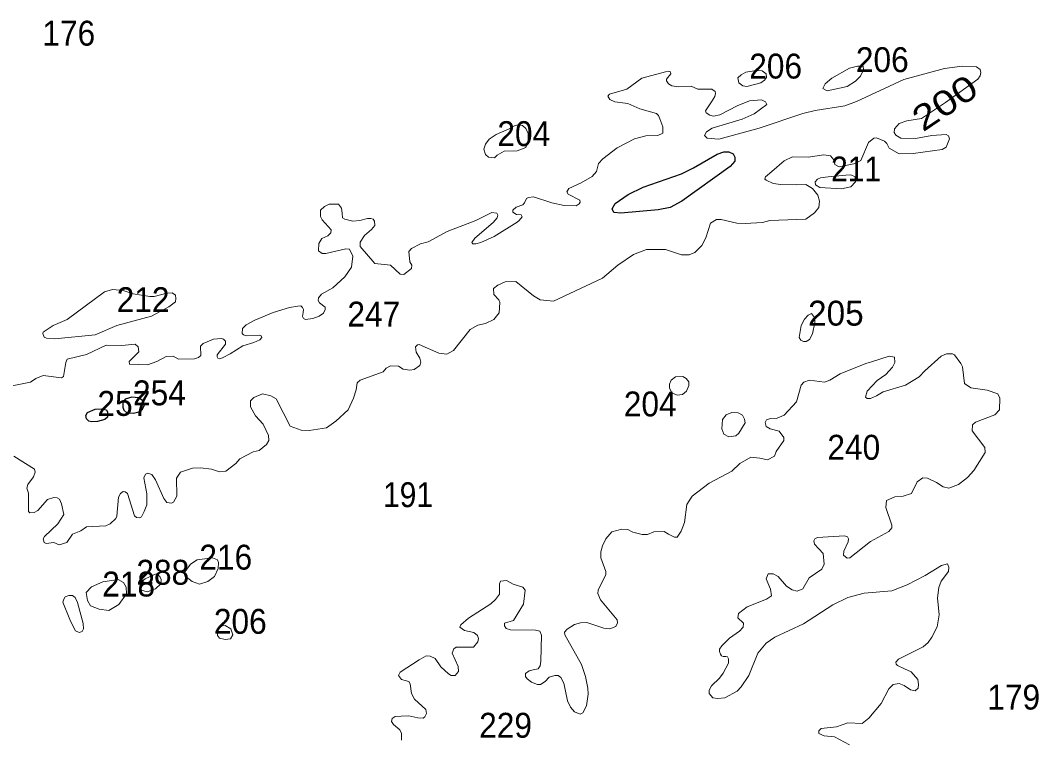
# Model space of a CAD drawing. Extents: x 499.9 to 555.3, y 9281.5 to 9336.8.
# Drawn here: x 505.67 to 512.21, y 9283.84 to 9288.46 of the extents above; entities that cross this region are included whole.
import ezdxf
from ezdxf.enums import TextEntityAlignment as Align

# ---------------------------------------------------------------- set-up
doc = ezdxf.new("R2010")
doc.units = 0
doc.header["$LTSCALE"] = 0.064
doc.layers.add('1', color=7, linetype='Continuous', lineweight=25)
doc.layers.add('2', color=7, linetype='Continuous', lineweight=13)
doc.layers.add('21', color=7, linetype='Continuous')
doc.layers.add('61', color=7, linetype='Continuous')

msp = doc.modelspace()

# ---------------------------------------------------------------- linework, layer by layer
at = {"layer": '1'}
for points in [[(509.5307, 9287.2221), (509.4853, 9287.2275), (509.4736, 9287.251), (509.4939, 9287.2848), (509.5766, 9287.3422), (509.6736, 9287.3907), (509.9187, 9287.4767), (509.9967, 9287.5134), (510.1479, 9287.6016), (510.1913, 9287.6169), (510.2227, 9287.6161), (510.2522, 9287.6051), (510.2617, 9287.5837), (510.2612, 9287.5561), (510.2313, 9287.5226), (509.9215, 9287.3004), (509.8463, 9287.2604), (509.7692, 9287.2442)], [(506.3575, 9285.9402), (506.401, 9285.9372), (506.4349, 9285.946), (506.4598, 9285.9634), (506.471, 9285.9912), (506.4569, 9286.0205), (506.4339, 9286.0368), (506.3907, 9286.0407), (506.3471, 9286.027), (506.3336, 9286.0076), (506.3319, 9285.9763), (506.3388, 9285.9565)], [(506.1154, 9285.8876), (506.1005, 9285.9012), (506.0947, 9285.9221), (506.1066, 9285.9424), (506.1552, 9285.9637), (506.1947, 9285.9655), (506.2278, 9285.9593), (506.235, 9285.9444), (506.2352, 9285.9132), (506.2182, 9285.8964), (506.1712, 9285.8843), (506.1334, 9285.8833)]]:
    msp.add_lwpolyline(points, close=True, dxfattribs=at)
at = {"layer": '2'}
for points in [[(508.8893, 9287.2114), (508.8601, 9287.2155), (508.8366, 9287.2292), (508.837, 9287.242), (508.8582, 9287.2621), (508.9002, 9287.2773), (508.9115, 9287.2892), (508.9235, 9287.3175), (508.9368, 9287.3235), (508.9701, 9287.328), (509.0871, 9287.2895), (509.166, 9287.2728), (509.2429, 9287.2698), (509.2615, 9287.2829), (509.269, 9287.2934), (509.2667, 9287.3069), (509.1913, 9287.3456), (509.183, 9287.3601), (509.1961, 9287.3812), (509.2747, 9287.4174), (509.3454, 9287.4595), (509.373, 9287.4902), (509.3866, 9287.5415), (509.4135, 9287.5717), (509.506, 9287.6425), (509.6172, 9287.6997), (509.6912, 9287.7196), (509.7683, 9287.7217), (509.7996, 9287.7377), (509.7999, 9287.7772), (509.7811, 9287.8289), (509.7723, 9287.8512), (509.7593, 9287.8624), (509.6522, 9287.8944), (509.5741, 9287.9282), (509.4915, 9287.9381), (509.4587, 9287.9536), (509.4475, 9287.9739), (509.4581, 9287.987), (509.5676, 9288.0199), (509.6641, 9288.0909), (509.8161, 9288.132), (509.8368, 9288.1363), (509.8498, 9288.1319), (509.8503, 9288.1189), (509.823, 9288.0835), (509.8225, 9288.0728), (509.8359, 9288.0544), (509.8576, 9288.0415), (509.9028, 9288.0351), (509.9808, 9288.038), (510.0238, 9288.0191), (510.1143, 9288.0202), (510.1354, 9288.0053), (510.1373, 9287.9927), (510.1345, 9287.9735), (510.1127, 9287.9384), (510.0743, 9287.8809), (510.0774, 9287.8681), (510.1017, 9287.8521), (510.1248, 9287.8473), (510.1662, 9287.8552), (510.2777, 9287.9126), (510.3565, 9287.9455), (510.4328, 9287.9521), (510.4587, 9287.9393), (510.4665, 9287.9205), (510.3865, 9287.8619), (510.3087, 9287.8279), (510.1171, 9287.7682), (510.081, 9287.7456), (510.0682, 9287.7231), (510.0852, 9287.7058), (510.1601, 9287.6976), (510.4177, 9287.7692), (510.6993, 9287.8627), (510.7782, 9287.8824), (510.9691, 9287.9127), (511.044, 9287.9408), (511.3472, 9288.0826), (511.608, 9288.1517), (511.7216, 9288.1683), (511.8124, 9288.1638), (511.836, 9288.1467), (511.8417, 9288.1263), (511.8375, 9288.106), (511.8209, 9288.0834), (511.6137, 9287.9347), (511.4609, 9287.832), (511.3654, 9287.8156), (511.3166, 9287.7982), (511.2864, 9287.7639), (511.2844, 9287.7416), (511.2947, 9287.7242), (511.3286, 9287.7042)], [(511.3286, 9287.7042), (511.421, 9287.7026), (511.5273, 9287.7217), (511.6188, 9287.7289), (511.6341, 9287.7203), (511.6406, 9287.6996)], [(511.6406, 9287.6996), (511.618, 9287.6474), (511.5928, 9287.6312), (511.4069, 9287.6058), (511.3162, 9287.6053), (511.2523, 9287.6416), (511.2388, 9287.6704), (511.2229, 9287.6863), (511.1708, 9287.707), (511.154, 9287.7049), (511.1208, 9287.6761), (511.0709, 9287.5619), (511.0265, 9287.5399), (510.9321, 9287.5217), (510.9038, 9287.5361), (510.897, 9287.5664), (510.8754, 9287.5909), (510.8338, 9287.5986), (510.7328, 9287.5831), (510.6318, 9287.5845), (510.5786, 9287.5594), (510.4987, 9287.4904), (510.459, 9287.4555), (510.4553, 9287.4416), (510.4625, 9287.434), (510.5076, 9287.4127), (510.5578, 9287.4064), (510.6605, 9287.4061), (510.7177, 9287.4065), (510.7614, 9287.3811), (510.7948, 9287.3383), (510.8051, 9287.2997), (510.8007, 9287.2597), (510.7725, 9287.2256), (510.7177, 9287.1841), (510.4858, 9287.175), (510.4389, 9287.1629), (510.3273, 9287.1565), (510.2745, 9287.1597), (510.1745, 9287.1816), (510.1449, 9287.1815), (510.106, 9287.1594), (510.0754, 9287.0642), (510.0509, 9287.015), (510.0047, 9286.97), (509.9688, 9286.9546), (509.9199, 9286.9559), (509.816, 9286.9892), (509.6944, 9286.989), (509.6117, 9286.957), (509.5099, 9286.8885), (509.4133, 9286.8062), (509.0972, 9286.6587), (509.0123, 9286.6672), (508.9687, 9286.6923), (508.8562, 9286.7837), (508.7876, 9286.7824), (508.7403, 9286.7601), (508.7133, 9286.7384), (508.715, 9286.7014), (508.7459, 9286.6668), (508.7529, 9286.6484), (508.7495, 9286.5835), (508.7145, 9286.5407), (508.6614, 9286.5149), (508.6129, 9286.5038), (508.5627, 9286.4756), (508.4555, 9286.3403), (508.413, 9286.3167), (508.3607, 9286.3229), (508.2353, 9286.3801), (508.2251, 9286.3777), (508.2126, 9286.3645), (508.2152, 9286.329), (508.2387, 9286.2922), (508.2464, 9286.2661), (508.2395, 9286.2441), (508.2022, 9286.2177), (508.1759, 9286.2144), (508.1321, 9286.2212), (508.1028, 9286.2397), (508.0502, 9286.2428), (508.0235, 9286.2263), (508.0039, 9286.203), (507.856, 9286.1493), (507.8365, 9286.1328), (507.8312, 9286.0869), (507.8135, 9286.0334), (507.7786, 9285.9596), (507.6993, 9285.8865), (507.6401, 9285.8446), (507.5298, 9285.826), (507.4774, 9285.8291), (507.4061, 9285.8553), (507.3166, 9286.0299)], [(506.9388, 9286.3136), (506.9379, 9286.3003), (506.9423, 9286.2906), (506.9539, 9286.2879), (506.9722, 9286.2941), (507.0215, 9286.3202), (507.1038, 9286.3714), (507.1748, 9286.3926), (507.2129, 9286.4095), (507.2256, 9286.4239), (507.2218, 9286.4352), (507.2132, 9286.4387), (507.1299, 9286.4344), (507.1075, 9286.4406), (507.0988, 9286.4505), (507.1019, 9286.4815), (507.1255, 9286.5048), (507.1803, 9286.5346), (507.2969, 9286.5841), (507.4033, 9286.6169), (507.4566, 9286.6262), (507.4746, 9286.6268), (507.487, 9286.6179), (507.4924, 9286.6046), (507.4913, 9286.5851), (507.4853, 9286.5585), (507.4937, 9286.5457), (507.5047, 9286.5405), (507.5527, 9286.5467), (507.5938, 9286.5623), (507.6203, 9286.5812), (507.6325, 9286.6046), (507.6308, 9286.6197), (507.5944, 9286.6463), (507.5864, 9286.6623), (507.5891, 9286.6787), (507.6087, 9286.7025), (507.6802, 9286.7443), (507.7585, 9286.8134), (507.801, 9286.8765), (507.8104, 9286.9471), (507.7873, 9286.9912), (507.7638, 9286.9938), (507.6357, 9286.9639), (507.6119, 9286.9642), (507.5885, 9286.9813), (507.5911, 9287.0286), (507.6108, 9287.0595), (507.6486, 9287.0777), (507.668, 9287.0967), (507.6706, 9287.1161), (507.6115, 9287.1797), (507.601, 9287.2012), (507.6008, 9287.2415), (507.6268, 9287.2657), (507.658, 9287.2803), (507.7174, 9287.2805), (507.7357, 9287.2551), (507.7415, 9287.222), (507.7441, 9287.1924), (507.7587, 9287.1838), (507.8094, 9287.1725), (507.8544, 9287.1755), (507.9038, 9287.1882), (507.9248, 9287.1891), (507.9407, 9287.1838), (507.9481, 9287.1708), (507.9501, 9287.1448), (507.9294, 9287.1178), (507.8849, 9287.08), (507.8574, 9287.0377), (507.8559, 9287.0079), (507.951, 9286.899), (508.0512, 9286.8895), (508.1126, 9286.8309), (508.137, 9286.8288), (508.1862, 9286.8675), (508.1876, 9286.889), (508.1753, 9286.9114), (508.1679, 9286.9771), (508.1871, 9286.9961), (508.2429, 9287.0255), (508.2929, 9287.0395), (508.4147, 9287.1052), (508.5983, 9287.1764), (508.7027, 9287.2279), (508.7338, 9287.2241), (508.7399, 9287.2098), (508.7364, 9287.1925), (508.7102, 9287.1634), (508.592, 9287.0622), (508.5726, 9287.0353), (508.5807, 9287.0269), (508.5995, 9287.0269), (508.632, 9287.0354)], [(508.632, 9287.0354), (508.7162, 9287.0738), (508.8644, 9287.1658), (508.878, 9287.1753), (508.8956, 9287.199), (508.8893, 9287.2114)], [(505.601, 9286.1087), (505.7409, 9286.1371), (505.7735, 9286.1616), (505.8213, 9286.1806), (505.9401, 9286.1655), (505.9525, 9286.1741), (505.9676, 9286.2644), (505.976, 9286.284), (506.1005, 9286.316), (506.2265, 9286.3747), (506.3273, 9286.3735), (506.4122, 9286.3823), (506.432, 9286.3652), (506.4351, 9286.3322), (506.3728, 9286.2703), (506.3752, 9286.2534), (506.492, 9286.2494), (506.5517, 9286.27), (506.6114, 9286.3018), (506.6551, 9286.3046), (506.6903, 9286.2845), (506.7921, 9286.2875), (506.8192, 9286.295), (506.8332, 9286.3089), (506.8306, 9286.3678), (506.848, 9286.386), (506.9155, 9286.4144)], [(506.9155, 9286.4144), (506.9663, 9286.4183), (506.9796, 9286.4139), (506.993, 9286.4003), (506.9921, 9286.3803), (506.9388, 9286.3136)], [(509.1443, 9284.239), (509.165, 9284.2025), (509.1885, 9284.0896), (509.2071, 9284.0492), (509.2331, 9284.0201), (509.2685, 9284.004), (509.2868, 9284.0129), (509.3087, 9284.0579), (509.3209, 9284.1318), (509.3192, 9284.1715), (509.3037, 9284.2464), (509.278, 9284.3235), (509.1714, 9284.5146), (509.1685, 9284.5312), (509.1859, 9284.551), (509.2329, 9284.5808), (509.271, 9284.5906), (509.3107, 9284.5922), (509.4215, 9284.5567), (509.4595, 9284.5529), (509.4969, 9284.5683), (509.5087, 9284.5904), (509.5068, 9284.6105), (509.4003, 9284.7388), (509.3832, 9284.7801), (509.3836, 9284.7999), (509.434, 9284.9011), (509.4338, 9284.9218), (509.4008, 9285.0079), (509.4025, 9285.0468), (509.4127, 9285.0858), (509.4337, 9285.131), (509.473, 9285.1766), (509.5367, 9285.1938), (509.5759, 9285.1897), (509.6064, 9285.1727), (509.6672, 9285.1575), (509.7014, 9285.1593), (509.742, 9285.1765), (509.8089, 9285.178), (509.836, 9285.1604), (509.8738, 9285.141), (509.8921, 9285.1407), (509.9163, 9285.1798), (509.9383, 9285.2363), (509.9545, 9285.3508), (509.9881, 9285.4055), (510.0963, 9285.4873), (510.2435, 9285.5645), (510.2936, 9285.6141), (510.3648, 9285.656), (510.4225, 9285.6489), (510.4722, 9285.6384), (510.5158, 9285.6609), (510.5278, 9285.691), (510.5771, 9285.7631), (510.5769, 9285.7818), (510.5472, 9285.823), (510.4887, 9285.8378), (510.4623, 9285.853), (510.4562, 9285.8786), (510.4661, 9285.8958), (510.4917, 9285.9043), (510.533, 9285.9049), (510.5795, 9285.9247), (510.6569, 9286.0113), (510.6867, 9286.1177), (510.7056, 9286.1378), (510.7406, 9286.1506), (510.8377, 9286.137), (510.8715, 9286.1492), (510.9384, 9286.1915), (511.1026, 9286.257), (511.1403, 9286.2672), (511.2526, 9286.3046), (511.2867, 9286.2984), (511.2895, 9286.2637), (511.2738, 9286.233), (511.2308, 9286.1857), (511.1753, 9286.1489), (511.1117, 9286.0788), (511.1001, 9286.0412), (511.1108, 9286.0327), (511.1333, 9286.0327), (511.172, 9286.049), (511.2142, 9286.0744), (511.3574, 9286.1175), (511.4451, 9286.1709), (511.4808, 9286.2109), (511.586, 9286.3048), (511.621, 9286.3191), (511.6588, 9286.3193), (511.6718, 9286.3127), (511.7137, 9286.2574), (511.7226, 9286.2349)], [(511.7226, 9286.2349), (511.7358, 9286.1285), (511.7777, 9286.1012), (511.8819, 9286.0868), (511.951, 9286.0615), (511.9642, 9286.0335)], [(507.3166, 9286.0299), (507.2831, 9286.0504), (507.229, 9286.0626), (507.1749, 9286.0379), (507.1522, 9286.0166), (507.1521, 9285.9788)], [(511.9642, 9286.0335), (511.9611, 9285.9598), (511.9301, 9285.9269), (511.8074, 9285.8808), (511.7881, 9285.8632), (511.7856, 9285.8254), (511.8659, 9285.7168), (511.8689, 9285.685), (511.7965, 9285.5688), (511.7546, 9285.5251), (511.698, 9285.4795), (511.6349, 9285.4552), (511.5998, 9285.4642), (511.5572, 9285.4932), (511.4986, 9285.521), (511.4698, 9285.5216), (511.4317, 9285.4961), (511.3956, 9285.4215), (511.3436, 9285.4047), (511.2891, 9285.4005), (511.2362, 9285.3762), (511.2312, 9285.3326), (511.2704, 9285.2188), (511.2701, 9285.2015), (511.2508, 9285.1778), (511.1337, 9285.1137), (511.0002, 9285.0081), (510.9836, 9285.0073), (510.9604, 9285.0253), (510.9606, 9285.0508), (510.9889, 9285.1116), (510.9916, 9285.1298), (510.985, 9285.1441), (510.967, 9285.15), (510.7924, 9285.1397), (510.7745, 9285.1307), (510.7695, 9285.1183), (510.7725, 9285.096), (510.8282, 9285.0356), (510.8346, 9284.9682), (510.8197, 9284.9359), (510.7383, 9284.8808), (510.6976, 9284.809), (510.6623, 9284.7946), (510.6292, 9284.8036), (510.5934, 9284.8264), (510.5395, 9284.8888), (510.5078, 9284.906), (510.4754, 9284.9056), (510.4628, 9284.8744), (510.4907, 9284.8073), (510.4965, 9284.764), (510.4654, 9284.7437), (510.3414, 9284.6946), (510.2851, 9284.6507), (510.2811, 9284.6236), (510.3185, 9284.589), (510.3155, 9284.5624), (510.2929, 9284.538), (510.2285, 9284.4923), (510.179, 9284.4437), (510.1634, 9284.4219), (510.1641, 9284.4067), (510.1698, 9284.3904), (510.1769, 9284.3794), (510.1867, 9284.3748), (510.2031, 9284.3743), (510.2155, 9284.3717), (510.2222, 9284.3588), (510.2212, 9284.3321), (510.1877, 9284.2682), (510.1629, 9284.2345), (510.1113, 9284.1866), (510.098, 9284.1579), (510.0978, 9284.1364), (510.1201, 9284.1084), (510.152, 9284.104), (510.1974, 9284.1087), (510.277, 9284.1528), (510.3035, 9284.1793), (510.3508, 9284.2534), (510.41, 9284.3962), (510.4639, 9284.4603), (510.5182, 9284.4993), (510.7026, 9284.5853), (510.891, 9284.7071), (510.9884, 9284.7545), (511.0925, 9284.7818), (511.2706, 9284.7955), (511.3685, 9284.8347), (511.4834, 9284.8945), (511.5879, 9284.9603), (511.628, 9284.9692), (511.6364, 9284.9496), (511.6332, 9284.9202)], [(507.1521, 9285.9788), (507.1843, 9285.9208), (507.2333, 9285.8665), (507.269, 9285.7949), (507.2694, 9285.7614), (507.2551, 9285.7369), (507.2074, 9285.6973), (507.1702, 9285.6902), (507.0848, 9285.6437), (507.0587, 9285.6153), (506.995, 9285.5649), (506.9537, 9285.5605), (506.9027, 9285.5777), (506.8316, 9285.587), (506.7794, 9285.5839), (506.7038, 9285.5587), (506.6777, 9285.5211), (506.6801, 9285.4051), (506.6586, 9285.3652), (506.6452, 9285.36), (506.6156, 9285.3647), (506.5965, 9285.389), (506.5415, 9285.509), (506.5186, 9285.5448), (506.4943, 9285.552), (506.4773, 9285.5468), (506.4677, 9285.5221), (506.4864, 9285.4193), (506.4865, 9285.3482), (506.4705, 9285.3071), (506.4532, 9285.2727), (506.4401, 9285.2648), (506.4205, 9285.267), (506.4069, 9285.2777), (506.3624, 9285.4223), (506.3481, 9285.4322), (506.3355, 9285.4338), (506.3183, 9285.4212), (506.3054, 9285.3977), (506.2946, 9285.2763), (506.2869, 9285.2603), (506.2511, 9285.2268), (506.2247, 9285.2133), (506.0989, 9285.2085), (506.0631, 9285.1815), (506.0099, 9285.1608), (505.9727, 9285.1071), (505.9236, 9285.0917), (505.8902, 9285.1062), (505.8401, 9285.101), (505.8276, 9285.108), (505.8216, 9285.1302), (505.8294, 9285.1447), (505.9145, 9285.2269), (505.9546, 9285.288), (505.9389, 9285.3547), (505.9257, 9285.3846), (505.9103, 9285.394), (505.8907, 9285.3955), (505.8499, 9285.3832), (505.7875, 9285.3133), (505.764, 9285.3002), (505.7366, 9285.2976), (505.7263, 9285.3067), (505.7272, 9285.4238), (505.7166, 9285.4566), (505.7231, 9285.4792), (505.759, 9285.53), (505.7694, 9285.5584), (505.7666, 9285.5791), (505.6325, 9285.6616)], [(511.6332, 9284.9202), (511.5876, 9284.8582), (511.5712, 9284.8183), (511.5636, 9284.7517), (511.573, 9284.6418), (511.5601, 9284.5648)], [(508.1226, 9283.8372), (508.1224, 9283.8793), (508.1104, 9283.9041), (508.0705, 9283.9387), (508.0585, 9283.9579), (508.0617, 9283.9767), (508.0805, 9283.9882), (508.1187, 9283.9923), (508.1698, 9283.9939), (508.2269, 9283.98), (508.2602, 9283.9784), (508.272, 9283.9877), (508.2815, 9284.0091), (508.2775, 9284.0346), (508.2052, 9284.0998), (508.1867, 9284.1375), (508.1785, 9284.1982), (508.168, 9284.2145), (508.1229, 9284.2266), (508.103, 9284.2523), (508.1128, 9284.275), (508.2344, 9284.3542), (508.2811, 9284.3781), (508.3056, 9284.3778), (508.337, 9284.3612), (508.3739, 9284.3082), (508.423, 9284.2643), (508.441, 9284.2518), (508.4655, 9284.253), (508.488, 9284.2789), (508.4859, 9284.3107), (508.448, 9284.3969), (508.4582, 9284.4246), (508.4724, 9284.435), (508.5834, 9284.4352), (508.6112, 9284.4685), (508.6165, 9284.4907), (508.6099, 9284.5092), (508.5866, 9284.5288), (508.5256, 9284.5426), (508.4973, 9284.5636), (508.5032, 9284.5782), (508.551, 9284.6217), (508.695, 9284.713), (508.7257, 9284.7405), (508.751, 9284.7755), (508.75, 9284.8423), (508.7578, 9284.8587), (508.7965, 9284.864), (508.8396, 9284.8389), (508.9008, 9284.8197), (508.9165, 9284.8), (508.9054, 9284.7105), (508.8413, 9284.607), (508.7821, 9284.5879), (508.7835, 9284.5712), (508.7943, 9284.5536), (508.8215, 9284.5462), (508.9821, 9284.5447), (509.0104, 9284.5379), (509.0212, 9284.5127), (509.017, 9284.3457), (509.0131, 9284.3152), (508.9987, 9284.2949), (508.9663, 9284.2883), (508.941, 9284.2823), (508.9176, 9284.2662), (508.918, 9284.247), (508.9286, 9284.2307), (508.9558, 9284.2102), (508.9957, 9284.1949), (509.0146, 9284.1945)], [(511.5601, 9284.5648), (511.527, 9284.4981), (511.503, 9284.4652), (511.4718, 9284.4371), (511.3129, 9284.3566), (511.2964, 9284.3388), (511.2978, 9284.3249), (511.3057, 9284.3166), (511.3511, 9284.2961), (511.3941, 9284.2769), (511.436, 9284.2263), (511.4412, 9284.1955), (511.4387, 9284.1703), (511.4202, 9284.1551), (511.3893, 9284.1611), (511.3492, 9284.1893), (511.3161, 9284.2006), (511.2794, 9284.1945), (511.2497, 9284.1668), (511.2022, 9284.0721), (511.1227, 9283.9782), (511.0803, 9283.9439), (510.9874, 9283.9477), (510.9142, 9283.9225), (510.8165, 9283.9127), (510.8014, 9283.8978), (510.8022, 9283.8808), (510.8349, 9283.8649), (510.9022, 9283.8583), (510.9978, 9283.8079)], [(509.0146, 9284.1945), (509.0451, 9284.2148), (509.0692, 9284.2419), (509.1062, 9284.2533), (509.1274, 9284.2519), (509.1443, 9284.239)]]:
    msp.add_lwpolyline(points, dxfattribs=at)
for points in [[(510.3393, 9288.0367), (510.4286, 9288.0612), (510.4529, 9288.0784), (510.4643, 9288.0947), (510.464, 9288.1185), (510.4384, 9288.1385), (510.3987, 9288.1388), (510.3333, 9288.1282), (510.3017, 9288.1117), (510.2809, 9288.0915), (510.288, 9288.0614), (510.3132, 9288.0402)], [(510.9824, 9288.0366), (511.0367, 9288.0703), (511.0683, 9288.1032), (511.088, 9288.1436), (511.0865, 9288.1678), (511.0501, 9288.1681), (510.9983, 9288.1547), (510.8849, 9288.0896), (510.8428, 9288.0539), (510.8275, 9288.0241), (510.8551, 9288.0081)], [(508.7369, 9287.5954), (508.7814, 9287.6221), (508.8639, 9287.6239), (508.9191, 9287.6441), (508.9352, 9287.6929), (508.9357, 9287.7357), (508.9199, 9287.766), (508.8977, 9287.787), (508.8732, 9287.7913), (508.8523, 9287.7868), (508.8141, 9287.7641), (508.7293, 9287.7282), (508.685, 9287.6986), (508.6602, 9287.6665), (508.6504, 9287.6336), (508.6614, 9287.5998), (508.6805, 9287.5826), (508.7199, 9287.5783)], [(510.8081, 9287.3887), (510.7799, 9287.405), (510.7784, 9287.4242), (510.7918, 9287.4406), (510.8111, 9287.4495), (510.8603, 9287.4566), (510.9743, 9287.468), (511.0068, 9287.4702), (511.0355, 9287.4562), (511.0365, 9287.4245), (511.0064, 9287.3928), (510.946, 9287.3798)], [(505.8862, 9286.5019), (505.9747, 9286.5397), (506.2151, 9286.7182), (506.2674, 9286.7327), (506.3342, 9286.7257), (506.3994, 9286.7056), (506.5056, 9286.687), (506.5349, 9286.6872), (506.6162, 9286.709), (506.6495, 9286.7105), (506.6702, 9286.6954), (506.6738, 9286.6739), (506.6701, 9286.6528), (506.6281, 9286.6212), (506.517, 9286.5606), (506.295, 9286.5005), (506.155, 9286.4415), (505.8952, 9286.4166), (505.8437, 9286.4197), (505.8286, 9286.4274), (505.8185, 9286.449), (505.8209, 9286.4582)], [(510.7408, 9286.4112), (510.7605, 9286.4479), (510.7753, 9286.5208), (510.7736, 9286.5523), (510.7538, 9286.5775), (510.7319, 9286.5673), (510.7089, 9286.5411), (510.6885, 9286.5019), (510.6749, 9286.4247), (510.6858, 9286.4068), (510.7032, 9286.3978), (510.7198, 9286.3976)], [(509.8417, 9286.1253), (509.8433, 9286.1014), (509.8579, 9286.0697), (509.8912, 9286.0528), (509.9263, 9286.059), (509.9518, 9286.079), (509.9676, 9286.1148), (509.9657, 9286.1401), (509.9491, 9286.1611), (509.9273, 9286.1742), (509.8799, 9286.1709), (509.8524, 9286.1508)], [(510.2244, 9285.7851), (510.2678, 9285.7925), (510.2865, 9285.8096), (510.3278, 9285.8751), (510.3235, 9285.9005), (510.3108, 9285.9249), (510.2837, 9285.9396), (510.2417, 9285.9424), (510.2056, 9285.9264), (510.1821, 9285.8974), (510.1794, 9285.8374), (510.1911, 9285.8022)], [(506.7301, 9284.8926), (506.7776, 9284.8566), (506.8242, 9284.8402), (506.8789, 9284.8555), (506.9212, 9284.889), (506.9457, 9284.9391), (506.9473, 9284.9788), (506.9396, 9284.9959), (506.9091, 9285.0096), (506.81, 9284.9947), (506.7678, 9284.968), (506.726, 9284.9121)], [(506.2054, 9284.8544), (506.1318, 9284.8221), (506.0977, 9284.7856), (506.105, 9284.7336), (506.1254, 9284.7009), (506.1813, 9284.6794), (506.2436, 9284.6705), (506.3067, 9284.708), (506.3558, 9284.7776), (506.3549, 9284.8195), (506.3362, 9284.8506), (506.3037, 9284.8695)], [(506.531, 9284.9), (506.4754, 9284.8729), (506.4453, 9284.8495), (506.4425, 9284.8249), (506.4526, 9284.8001), (506.4896, 9284.7906), (506.5428, 9284.8085), (506.5771, 9284.8415), (506.5789, 9284.8692), (506.5713, 9284.8893), (506.5489, 9284.9054)], [(505.9485, 9284.7232), (505.993, 9284.612), (506.0133, 9284.5665), (506.0298, 9284.5394), (506.053, 9284.5297), (506.0714, 9284.5346), (506.0801, 9284.552), (506.0791, 9284.5868), (506.0423, 9284.7213), (506.0269, 9284.7532), (506.0104, 9284.7667), (505.9872, 9284.7667), (505.963, 9284.7571), (505.9533, 9284.7426)], [(507.0244, 9284.4878), (506.9901, 9284.4848), (506.9532, 9284.4926), (506.9415, 9284.5088), (506.9425, 9284.5388), (506.958, 9284.5699), (506.9908, 9284.573), (507.0255, 9284.5531), (507.0386, 9284.5132)]]:
    msp.add_lwpolyline(points, close=True, dxfattribs=at)

# ---------------------------------------------------------------- texts
at = {"layer": '21'}
for s, width, p in [('176', 0.95, (505.8161, 9288.2995)), ('206', 0.95, (510.3544, 9288.0879)), ('206', 0.95, (511.039, 9288.1292)), ('204', 0.95, (508.7373, 9287.654)), ('211', 0.9, (510.8796, 9287.427)), ('212', 0.95, (506.2932, 9286.5873)), ('247', 0.95, (507.7747, 9286.4947)), ('254', 0.95, (506.3982, 9285.9885)), ('257', 0.95, (506.1698, 9285.9206)), ('240', 0.95, (510.856, 9285.6389)), ('191', 0.9, (508.0031, 9285.3342)), ('216', 0.95, (506.8241, 9284.9329)), ('288', 0.95, (506.4198, 9284.8358)), ('218', 0.95, (506.2006, 9284.7601)), ('206', 0.95, (506.9173, 9284.5204)), ('179', 0.95, (511.8828, 9284.0338)), ('229', 0.95, (508.6204, 9283.8527))]:
    msp.add_text(s, height=0.16, dxfattribs=dict(at, width=width)).set_placement(p)
msp.add_text('205', height=0.16, dxfattribs=at).set_placement((510.7321, 9286.5005))
at = {"layer": '21', "width": 0.95}
msp.add_text('204', height=0.16, dxfattribs=at).set_placement((509.8883, 9285.9171), align=Align.RIGHT)
at = {"layer": '61', "width": 1.25}
msp.add_text('200', height=0.16, rotation=33.896, dxfattribs=at).set_placement((511.6546, 9287.8658), align=Align.CENTER)

doc.saveas('drawing.dxf')
